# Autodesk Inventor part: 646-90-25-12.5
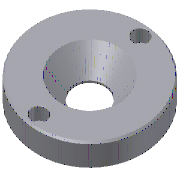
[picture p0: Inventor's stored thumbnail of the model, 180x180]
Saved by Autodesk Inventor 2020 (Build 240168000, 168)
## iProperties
Created: 2019-01
Part Number: 646-90-25-12.5
Material: ANFOR XC 38 TS
Description: Locating Ring
Document SubType Name: Modeling
Designer: LENOVO-CADCIM
Standard Revision: 1
Manufacturer: RABOURDIN
Language: en-US
Size Designation: 646-90-25-12.5
Categories: <MemberInstance><Categories><Category DisplayName="Mold" InternalName="349578f2-f4d4-4954-8c09-8e99297a61c0" Mnemonic="MOLD"><Category DisplayName="Locatings" I
Density: 7.845 g/cm^3
Appearance: Default
IsCustomPart: 1
Author: LENOVO-CADCIM
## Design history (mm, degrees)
sketch "Sketch1"
  geometry: L1 (0, -2.5)-(0, 15) reference; L2 (24, 12.5)-(12.5, 1); L3 (12.5, 1)-(12.5, 0); L4 (12.5, 0)-(45, 0); L5 (45, 0)-(45, 12.5); L6 (45, 12.5)-(24, 12.5); 1 further point
  constraints: 10 end point, 2 horizontal, 2 vertical, 1 point on line
  dimensions: "d0" = 45 deg angle of L1 L2; "d1" = 25 diameter of L3 L1 (= D2); "d2" = 90 diameter of L5 L1 (= D1); "d3" = 12.5 distance between parallel lines of L4 L6 (= A_); "d4" = 1 distance from line of L2.end L4 (= C_)
revolve "Revolution1" sketch "Sketch1" stored, may be unused: angle "d5" = 90 deg
sketch "Sketch2"
  geometry: 3 further points
  constraints: 2 vertical alignment
  dimensions: "d29" = 37 distance of point (0, 0) point (0, 37); "d30" = 37 distance of point (0, -37) point (0, 0)
hole "Hole1" sketch "Sketch2" diameter "d7" = 7; stored, may be unused: countersink angle "d11" = 90 deg, drill point angle "d13" = 0 deg; dims "d8" = 6, "d9" = 11, "d10" = 7, "d12" = 12.5 (= A_)
hole "Hole2" sketch "Sketch2" diameter "d31" = 7; stored, may be unused: countersink angle "d35" = 90 deg, drill point angle "d37" = 0 deg; dims "d32" = 6, "d33" = 11, "d34" = 7, "d36" = 12.5 (= A_)
chamfer "Chamfer1" distance "d14" = 1; stored, may be unused: second distance "d15" = 2, angle "d16" = 45 deg
chamfer "Chamfer2" distance "d17" = 0.5; stored, may be unused: second distance "d18" = 2, angle "d19" = 45 deg
chamfer "Chamfer3" distance "d20" = 0.3; stored, may be unused: second distance "d21" = 2, angle "d22" = 45 deg
sketch "Sketch3"
  geometry: L1 (0, -2.5)-(0, 15) reference; L2 (0, 0)-(45, 0); L3 (45, 0)-(45, 12.5); L4 (45, 12.5)-(0, 12.5); L5 (0, 12.5)-(0, 0)
  constraints: 8 end point, 2 parallel, 1 horizontal, 1 perpendicular
  dimensions: "d23" = 90 diameter of L3 L1 (= D1_CS); "d24" = 12.5 distance between parallel lines of L2 L4 (= A_CS)
feature "RevolutionSrf1" sketch "Sketch3" dims angle "d25" = 90 deg
body "Solid1"
body "Srf1"
other parameters: "D1" = 90 [user parameter; used in 1 equation term], "D2" = 25 [user parameter; used in 1 equation term], "A_" = 12.5 [user parameter; used in 3 equation terms], "C_" = 1 [user parameter; used in 1 equation term], "D1_CS" = 90 [user parameter; used in 1 equation term], "A_CS" = 12.5 [user parameter; used in 1 equation term], "d26" = 0, "d27" = 0, "d28" = 0
